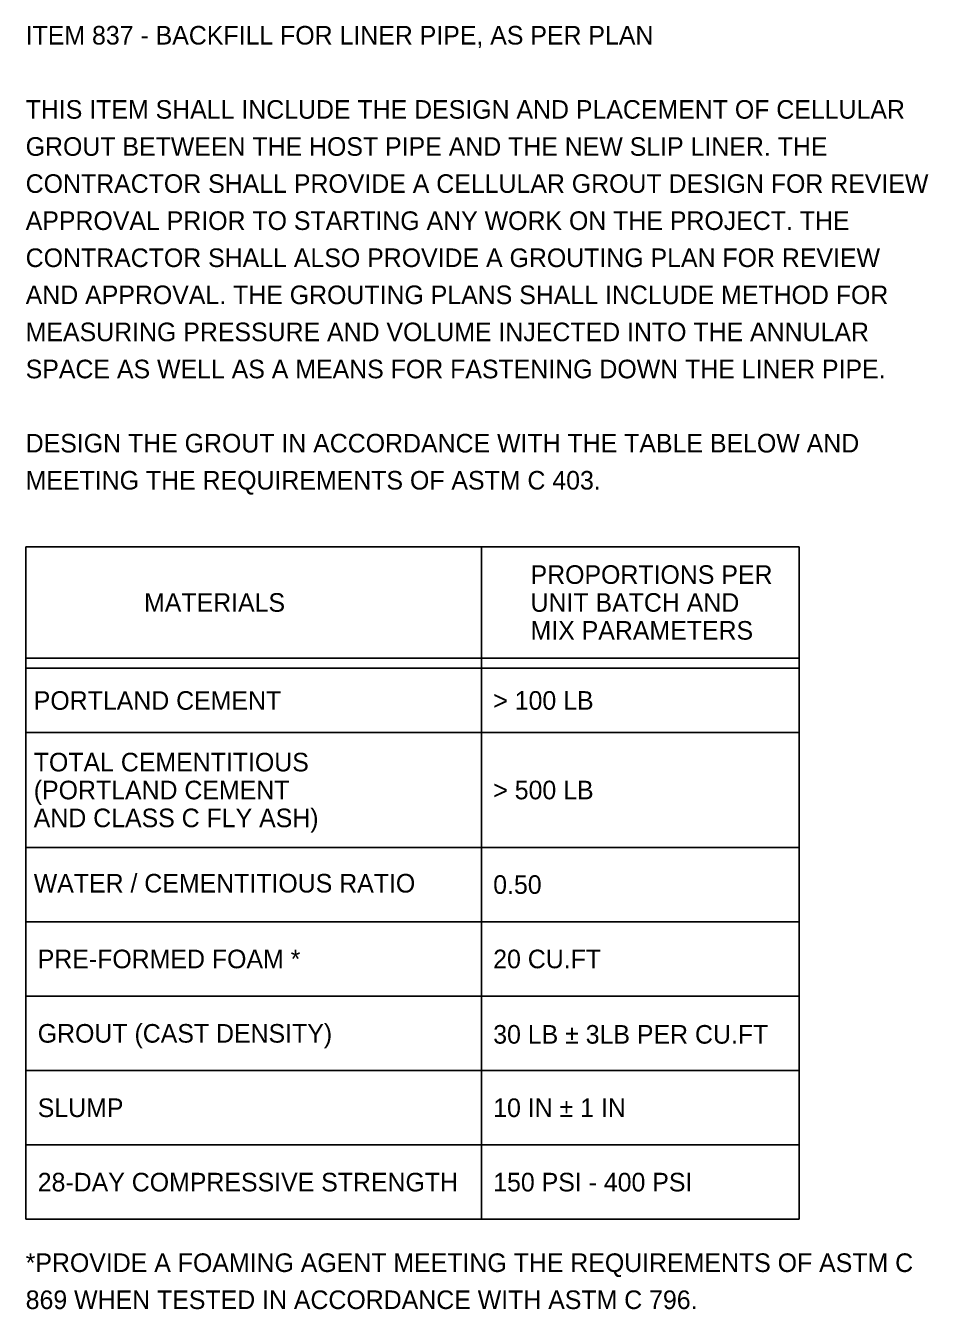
# Model space of a CAD drawing. Extents: x 0 to 34, y -12.9 to 22.
# Drawn here: x 9.82 to 16.61, y -12.88 to -3.22 of the extents above; entities that cross this region are included whole.
import ezdxf

# ---------------------------------------------------------------- set-up
doc = ezdxf.new("R2010")
doc.units = 0
doc.layers.add('SH_Text', color=7, linetype='Continuous')

msp = doc.modelspace()

# ---------------------------------------------------------------- linework, layer by layer
at = {"layer": 'SH_Text'}
for p, q in [((9.82, -7.14), (15.6415, -7.14)), ((9.82, -7.14), (9.82, -12.2036)), ((13.2501, -7.14), (13.2501, -12.2036)), ((15.6415, -7.14), (15.6415, -12.2036)), ((9.82, -7.98), (15.6415, -7.98)), ((9.82, -8.055), (15.6415, -8.055)), ((9.82, -8.54), (15.6415, -8.54)), ((9.82, -9.4036), (15.6415, -9.4036)), ((9.82, -9.4036), (15.6415, -9.4036)), ((9.82, -9.9636), (15.6415, -9.9636)), ((9.82, -10.5236), (15.6415, -10.5236)), ((9.82, -11.0836), (15.6415, -11.0836)), ((9.82, -11.6436), (15.6415, -11.6436)), ((9.82, -12.2036), (15.6415, -12.2036))]:
    msp.add_line(p, q, dxfattribs=at)

# ---------------------------------------------------------------- texts
for s, p in [('ITEM 837 - BACKFILL FOR LINER PIPE, AS PER PLAN', (9.82, -3.36)), ('THIS ITEM SHALL INCLUDE THE DESIGN AND PLACEMENT OF CELLULAR ', (9.82, -3.9183)), ('GROUT BETWEEN THE HOST PIPE AND THE NEW SLIP LINER. THE ', (9.82, -4.1975)), ('CONTRACTOR SHALL PROVIDE A CELLULAR GROUT DESIGN FOR REVIEW ', (9.82, -4.4766)), ('APPROVAL PRIOR TO STARTING ANY WORK ON THE PROJECT. THE ', (9.82, -4.7558)), ('CONTRACTOR SHALL ALSO PROVIDE A GROUTING PLAN FOR REVIEW', (9.82, -5.035)), ('AND APPROVAL. THE GROUTING PLANS SHALL INCLUDE METHOD FOR ', (9.82, -5.3141)), ('MEASURING PRESSURE AND VOLUME INJECTED INTO THE ANNULAR ', (9.82, -5.5933)), ('SPACE AS WELL AS A MEANS FOR FASTENING DOWN THE LINER PIPE.', (9.82, -5.8725)), ('DESIGN THE GROUT IN ACCORDANCE WITH THE TABLE BELOW AND ', (9.82, -6.4308)), ('MEETING THE REQUIREMENTS OF ASTM C 403.', (9.82, -6.71)), ('PROPORTIONS PER', (13.619, -7.42)), ('MATERIALS', (10.7108, -7.63)), ('UNIT BATCH AND', (13.619, -7.63)), ('MIX PARAMETERS', (13.619, -7.84)), ('PORTLAND CEMENT', (9.8807, -8.368)), ('>', (13.3381, -8.3675)), (' 100 LB', (13.448, -8.3675)), ('TOTAL CEMENTITIOUS', (9.8807, -8.8318)), ('(PORTLAND CEMENT', (9.8807, -9.0418)), ('>', (13.3381, -9.0418)), (' 500 LB', (13.448, -9.0418)), ('AND CLASS C FLY ASH)', (9.8807, -9.2518)), ('WATER / CEMENTITIOUS RATIO', (9.8807, -9.7434)), ('0.50', (13.3381, -9.7536)), ('PRE-FORMED FOAM *', (9.9107, -10.3136)), ('20 CU.FT', (13.3381, -10.3136)), ('GROUT (CAST DENSITY)', (9.9107, -10.8736)), ('30 LB ± 3LB PER CU.FT', (13.3381, -10.8811)), ('SLUMP', (9.9107, -11.4336)), ('10 IN ± 1 IN', (13.3381, -11.4336)), ('28-DAY COMPRESSIVE STRENGTH', (9.9107, -11.9936)), ('150 PSI - 400 PSI', (13.3381, -11.9936)), ('*PROVIDE A FOAMING AGENT MEETING THE REQUIREMENTS OF ASTM C ', (9.82, -12.6)), ('869 WHEN TESTED IN ACCORDANCE WITH ASTM C 796.', (9.82, -12.8791))]:
    msp.add_text(s, height=0.14, dxfattribs=at).set_placement(p)

doc.saveas('drawing.dxf')
